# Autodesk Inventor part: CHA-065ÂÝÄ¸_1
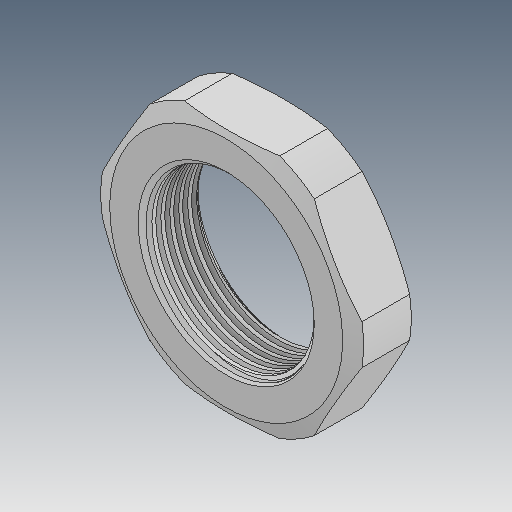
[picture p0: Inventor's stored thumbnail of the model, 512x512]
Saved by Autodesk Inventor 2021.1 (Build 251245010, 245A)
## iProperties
Created: 2019-12
Part Number: CHA-065ÂÝÄ¸_1
Material: Ogólny
Document SubType Name: Modeling
Designer: user
Density: 1 g/cm^3
Appearance: Domyślna
Author: user
Revision Number: ÈÎºÎ
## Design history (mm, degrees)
feature "ÊäÈë1"
node "Bryła1"
